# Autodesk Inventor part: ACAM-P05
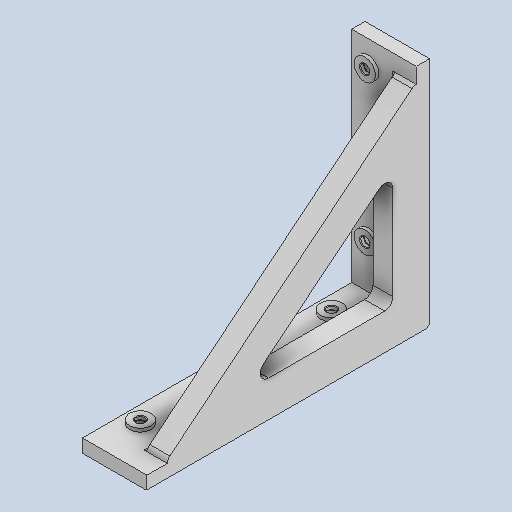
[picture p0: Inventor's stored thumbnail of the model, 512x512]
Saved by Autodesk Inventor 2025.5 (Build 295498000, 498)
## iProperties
Company: Open CASCADE
Created: 2026-10
Part Number: ACAM-P05
Material: Genérico
Description: Cartabón derecho
Document SubType Name: Modeling
Designer: Luis M
Authority: Unknown
Density: 1 g/cm^3
Appearance: Valor por defecto
Sending System: Open CASCADE 7.9
Preprocessor: Open CASCADE STEP processor 7.9
Material_BOM: PLA
Proceso_BOM: Impresión 3D
Title: Open CASCADE Shape Model
Author: Author
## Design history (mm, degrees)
feature "Base1"
node "Sólido1"
